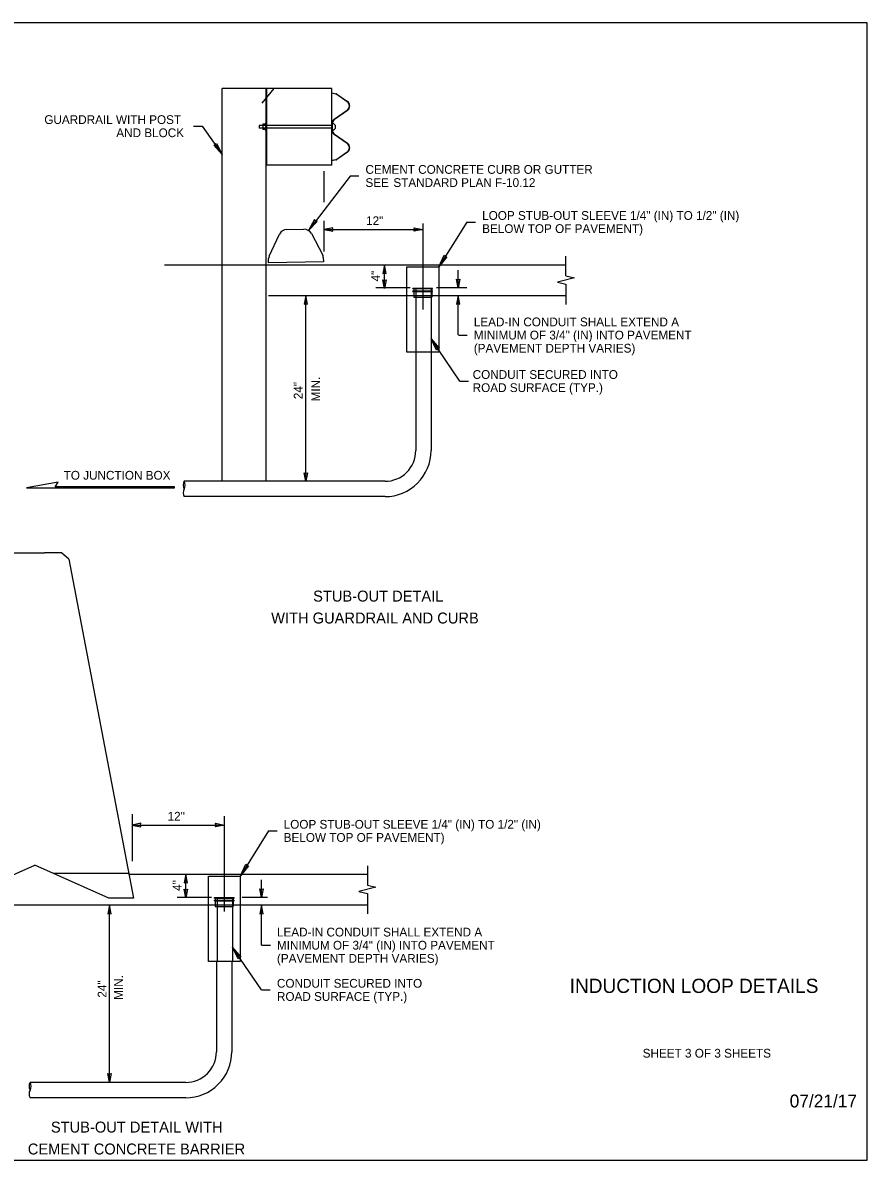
# Model space of a CAD drawing. Extents: x 99862 to 103151, y 100000 to 108153.
# Drawn here: x 101610 to 103151, y 106000 to 108076 of the extents above; entities that cross this region are included whole.
import ezdxf

# ---------------------------------------------------------------- set-up
doc = ezdxf.new("R2010")
doc.units = 0
for name, color, linetype in [('Level 1', 7, 'Continuous'), ('Level 10', 7, 'Continuous'), ('Level 11', 7, 'Continuous'), ('Level 15', 7, 'Continuous'), ('Level 18', 7, 'Continuous'), ('Level 2', 7, 'Continuous'), ('Level 20', 7, 'Continuous'), ('Level 22', 7, 'Continuous'), ('Level 27', 7, 'Continuous'), ('Level 5', 7, 'Continuous'), ('Level 60', 7, 'Continuous'), ('Level 62', 7, 'Continuous')]:
    doc.layers.add(name, color=color, linetype=linetype)

msp = doc.modelspace()

# ---------------------------------------------------------------- linework, layer by layer
at = {"layer": 'Level 1'}
for p, q in [((102053.9, 107955.6), (101973.9, 107955.6)), ((101973.9, 107633.3), (101973.9, 107955.6)), ((102053.9, 107634.9), (102053.9, 107955.6))]:
    msp.add_line(p, q, dxfattribs=at)
msp.add_lwpolyline([(99862, 105999.5), (103151, 105999.5), (103151, 108075.5), (99862, 108075.5)], close=True, dxfattribs=at)
at = {"layer": 'Level 10'}
for p, q in [((102173.9, 107955.6), (102053.9, 107955.6)), ((102054.9, 107815.6), (102054.9, 107955.6)), ((102173.9, 107815.6), (102173.9, 107955.6)), ((102173.9, 107815.6), (102053.9, 107815.6)), ((102601.1, 107633.3), (101868.6, 107633.3)), ((101973.9, 107238.6), (101973.9, 107633.3)), ((102053.9, 107238.6), (102053.9, 107634.9)), ((102319.5, 107577.3), (102057.9, 107577.3)), ((102361.1, 107577.3), (102319.4, 107577.3)), ((102601.1, 107577.3), (102361.1, 107577.3)), ((102238.8, 106521.1), (101803.4, 106521.1)), ((101957.1, 106465.1), (101334.5, 106465.1)), ((101998.8, 106465.1), (101957, 106465.1)), ((102238.8, 106465.1), (101998.8, 106465.1))]:
    msp.add_line(p, q, dxfattribs=at)
at = {"layer": 'Level 11'}
for p, q in [((101582.9, 107107.8), (101613.9, 107107.8)), ((101613.9, 107107.8), (101649.4, 107107.8)), ((101680.4, 107107.8), (101649.4, 107107.8)), ((101693.8, 107096.8), (101680.4, 107107.8)), ((101693.8, 107096.8), (101811.6, 106477.9)), ((101496.6, 106477.9), (101631.6, 106537.9)), ((101766.6, 106477.9), (101631.7, 106537.9)), ((101811.6, 106477.9), (101766.6, 106477.9))]:
    msp.add_line(p, q, dxfattribs=at)
for points in [[(102310.9, 107630.3), (102369.1, 107630.3), (102369.1, 107474.2), (102310.9, 107474.2)], [(101948.5, 106518), (102006.7, 106518), (102006.7, 106362), (101948.5, 106362)]]:
    msp.add_lwpolyline(points, close=True, dxfattribs=at)
at = {"layer": 'Level 15'}
for p, q in [((101921, 107886.7), (101937, 107886.7)), ((102223.1, 107795.8), (102207.1, 107795.8)), ((102339.6, 107709.1), (102339.9, 107552.2)), ((102420.1, 107711.8), (102369.1, 107630.3)), ((102420.1, 107711.8), (102436.1, 107711.8)), ((102269.8, 107591.6), (102269.8, 107633.7)), ((102404.3, 107591.9), (102404.3, 107623.9)), ((102316.5, 107591.6), (102253.8, 107591.6)), ((102420.3, 107591.7), (102364.5, 107591.7)), ((102404.3, 107505.7), (102404.3, 107577.5)), ((102407.3, 107421.5), (102354.8, 107498.8)), ((102404.9, 107505.5), (102420.9, 107505.5)), ((102407.3, 107421.5), (102423.3, 107421.5)), ((101809.5, 106631.1), (101809.5, 106545.6)), ((101977.5, 106627.3), (101977.5, 106453.5)), ((102057.9, 106600.6), (102006.9, 106518.8)), ((102057.9, 106600.6), (102073.9, 106600.6)), ((101907.4, 106479.3), (101907.4, 106521.5)), ((102238.8, 106537.1), (102238.8, 106501.6)), ((102045.6, 106479.3), (102045.6, 106511.3)), ((101954.1, 106479.3), (101891.4, 106479.3)), ((102056.4, 106479.1), (102009.9, 106479.1)), ((102238.8, 106486.1), (102238.8, 106449.1)), ((102045.6, 106391.9), (102045.6, 106464.9)), ((102045.1, 106310.4), (101992.6, 106387.6)), ((102045.6, 106391.9), (102061.6, 106391.9)), ((102045.1, 106310.4), (102061.1, 106310.4))]:
    msp.add_line(p, q, dxfattribs=at)
for points in [[(101937, 107886.7), (101973.9, 107835.1)], [(102207.1, 107795.8), (102130.9, 107696.6)], [(102159.8, 107748.3), (102159.8, 107804.5)], [(102159.8, 107658), (102159.8, 107714.2)], [(102159.8, 107698.2), (102339.8, 107698.2)], [(102601.1, 107613.8), (102616.6, 107609.9), (102585.6, 107602.2), (102601.1, 107598.3)], [(102126.3, 107238.6), (102126.3, 107577.3)], [(101809.5, 106611.3), (101977.5, 106611.3)], [(102238.8, 106501.6), (102254.3, 106497.7), (102223.3, 106489.9), (102238.8, 106486.1)], [(101767.8, 106142.3), (101767.8, 106465.1)]]:
    msp.add_lwpolyline(points, dxfattribs=at)
for points in [[(101973.9, 107835.1), (101958.2, 107851.9), (101961.2, 107852.8), (101963.1, 107855.4)], [(102130.9, 107696.6), (102147.1, 107712.9), (102144.1, 107713.9), (102142.4, 107716.5)], [(102159.8, 107698.2), (102175.5, 107695.1), (102174.8, 107698.2), (102175.5, 107701.2)], [(102339.8, 107698.2), (102324.1, 107695.1), (102324.8, 107698.2), (102324.1, 107701.2)], [(102369.1, 107630.3), (102378.8, 107651.2), (102380.8, 107648.7), (102383.8, 107648)], [(102269.8, 107633.7), (102266.7, 107618), (102269.8, 107618.7), (102272.9, 107618)], [(102269.8, 107590.7), (102266.7, 107606.4), (102269.8, 107605.7), (102272.9, 107606.4)], [(102404.3, 107591.9), (102401.2, 107607.6), (102404.3, 107606.9), (102407.4, 107607.6)], [(102126.3, 107577.3), (102123.2, 107561.6), (102126.3, 107562.3), (102129.4, 107561.6)], [(102404.3, 107577.5), (102401.2, 107561.8), (102404.3, 107562.5), (102407.4, 107561.8)], [(102354.8, 107498.8), (102369.9, 107481.5), (102366.9, 107480.7), (102365, 107478.1)], [(102126.3, 107238.6), (102123.2, 107254.3), (102126.3, 107253.6), (102129.4, 107254.3)], [(101809.5, 106611.3), (101825.2, 106608.3), (101824.4, 106611.3), (101825.2, 106614.4)], [(101977.5, 106611.3), (101961.7, 106608.3), (101962.5, 106611.3), (101961.7, 106614.4)], [(101907.4, 106521.5), (101904.3, 106505.7), (101907.4, 106506.5), (101910.5, 106505.7)], [(102006.9, 106518.8), (102016.5, 106539.7), (102018.4, 106537.2), (102021.5, 106536.6)], [(101907.4, 106478.4), (101904.3, 106494.1), (101907.4, 106493.4), (101910.5, 106494.1)], [(102045.6, 106479.3), (102042.5, 106495.1), (102045.6, 106494.3), (102048.7, 106495.1)], [(101767.8, 106465.1), (101764.7, 106449.4), (101767.8, 106450.1), (101770.9, 106449.4)], [(102045.6, 106464.9), (102042.5, 106449.2), (102045.6, 106449.9), (102048.7, 106449.2)], [(101992.6, 106387.6), (102007.8, 106370.3), (102004.7, 106369.5), (102002.8, 106366.9)], [(101767.8, 106142.3), (101764.7, 106158), (101767.8, 106157.3), (101770.9, 106158)]]:
    msp.add_lwpolyline(points, close=True, dxfattribs=at)
for centre, start, end in [((101916.4, 107231.6), 150, 210), ((101892.2, 107231.6), 330, 30), ((101916.4, 107217.6), 150, 210), ((101635.1, 106134.5), 150, 210), ((101635.1, 106120.5), 150, 210), ((101610.8, 106134.5), 330, 30)]:
    msp.add_arc(centre, 14, start, end, dxfattribs=at)
at = {"layer": 'Level 18'}
for p, q in [((102068.2, 107955.6), (102045.9, 107928.6)), ((102173.9, 107947.3), (102181.3, 107946)), ((102181.2, 107945.4), (102173.9, 107946.7)), ((102201.8, 107931.4), (102182.7, 107944.8)), ((102183.1, 107945.3), (102202.2, 107931.9)), ((102178.1, 107899.4), (102201.8, 107916)), ((102202.2, 107915.5), (102178.5, 107898.9)), ((102047.6, 107890.6), (102047.6, 107880.6)), ((102052.6, 107890.6), (102047.6, 107890.6)), ((102052.6, 107893.1), (102052.6, 107888.1)), ((102054, 107893.1), (102052.6, 107893.1)), ((102174.5, 107879.3), (102174.5, 107891.8)), ((102174.5, 107891.2), (102174.5, 107879.9)), ((102173.9, 107888.1), (102040.9, 107888.1)), ((102052.6, 107888.1), (102040.9, 107888.1)), ((102040.9, 107888.1), (102040.9, 107883.1)), ((102173.9, 107883.1), (102040.9, 107883.1)), ((102052.6, 107883.1), (102040.9, 107883.1)), ((102052.6, 107880.6), (102047.6, 107880.6)), ((102052.6, 107888.1), (102052.6, 107883.1)), ((102052.6, 107883.1), (102052.6, 107878.1)), ((102054, 107878.1), (102052.6, 107878.1)), ((102201.8, 107855.1), (102178.1, 107871.8)), ((102178.5, 107872.3), (102202.2, 107855.6)), ((102182.7, 107826.4), (102201.8, 107839.8)), ((102202.2, 107839.3), (102183.1, 107825.9)), ((102173.9, 107824.4), (102181.2, 107825.7)), ((102181.3, 107825.1), (102173.9, 107823.8))]:
    msp.add_line(p, q, dxfattribs=at)
for centre, radius, start, end in [((102180.6, 107941.7), 3.75, 54.852, 80), ((102180.6, 107941.7), 4.38, 54.852, 80), ((102196.4, 107923.7), 9.38, 305.1461, 54.8378), ((102196.4, 107923.7), 10, 305.1461, 54.8378), ((102183.9, 107891.2), 10, 125.1612, 179.9985), ((102183.9, 107891.2), 9.38, 125.1612, 180), ((102174.5, 107885.6), 6.25, 270, 90), ((102183.9, 107879.9), 10, 180.0103, 234.8388), ((102183.9, 107879.9), 9.38, 180.0103, 234.8388), ((102196.4, 107847.4), 9.38, 305.1426, 54.8569), ((102196.4, 107847.4), 10, 305.1426, 54.8569), ((102180.6, 107829.4), 3.75, 280, 305.1437), ((102180.6, 107829.4), 4.38, 280, 305.1437)]:
    msp.add_arc(centre, radius, start, end, dxfattribs=at)
at = {"layer": 'Level 2'}
for p, q in [((102601.1, 107613.8), (102601.1, 107649.3)), ((102321.8, 107591.2), (102357.8, 107591.2)), ((102321.8, 107590.2), (102321.8, 107591.2)), ((102321.8, 107590.2), (102357.8, 107590.2)), ((102321.8, 107586.2), (102357.8, 107586.2)), ((102321.8, 107585.2), (102321.8, 107586.2)), ((102321.8, 107585.2), (102357.8, 107585.2)), ((102323.4, 107590.2), (102323.4, 107586.2)), ((102323.4, 107585.2), (102323.4, 107574.8)), ((102356.2, 107590.2), (102356.2, 107586.2)), ((102356.2, 107585.2), (102356.2, 107574.8)), ((102357.8, 107590.2), (102357.8, 107591.2)), ((102357.8, 107585.2), (102357.8, 107586.2)), ((102601.1, 107598.3), (102601.1, 107561.3)), ((102323.4, 107574.8), (102356.2, 107574.8)), ((101803, 106522.9), (101665.4, 106522.9)), ((101959.4, 106479), (101995.5, 106479)), ((101959.4, 106478), (101959.4, 106479)), ((101995.5, 106478), (101995.5, 106479)), ((101959.4, 106478), (101995.5, 106478)), ((101959.4, 106474), (101995.5, 106474)), ((101959.4, 106473), (101959.4, 106474)), ((101959.4, 106473), (101995.5, 106473)), ((101961, 106478), (101961, 106474)), ((101961, 106473), (101961, 106462.5)), ((101961, 106462.5), (101993.9, 106462.5)), ((101993.9, 106478), (101993.9, 106474)), ((101993.9, 106472.9), (101993.9, 106462.5)), ((101995.5, 106473), (101995.5, 106474))]:
    msp.add_line(p, q, dxfattribs=at)
at = {"layer": 'Level 20'}
msp.add_lwpolyline([(101886.7, 107228.3), (101669, 107228.3), (101674, 107236.9), (101616.3, 107226.7), (101886.7, 107226.7)], close=True, dxfattribs=at)
at = {"layer": 'Level 22'}
for p, q in [((102350.8, 107590.2), (102329.5, 107590.2)), ((101988.4, 106478), (101967.1, 106478))]:
    msp.add_line(p, q, dxfattribs=at)
at = {"layer": 'Level 27'}
for points in [[(102059.2, 107649.5), (102078.2, 107689.5)], [(102091.5, 107698.1), (102122.9, 107698.7), (102122.9, 107698.7)], [(102136.5, 107690.7), (102157.1, 107651.5)], [(102158.2, 107647), (102158.4, 107639.4), (102058.4, 107637.4), (102058.3, 107645)]]:
    msp.add_lwpolyline(points, dxfattribs=at)
for centre, radius, start, end in [((102091.8, 107683.1), 15, 91.1458, 154.5807), ((102123.2, 107683.7), 15, 27.7108, 91.1455), ((102068.3, 107645.2), 10, 154.5807, 181.1458), ((102148.2, 107646.8), 10, 1.1458, 27.7108)]:
    msp.add_arc(centre, radius, start, end, dxfattribs=at)
at = {"layer": 'Level 5'}
for p, q in [((102326.8, 107474.2), (102326.8, 107294.6)), ((102354.8, 107474.2), (102354.8, 107294.6)), ((102058.2, 107238.6), (101974.1, 107238.6)), ((102270.8, 107238.6), (102053.9, 107238.6)), ((101973.9, 107210.6), (101904.3, 107210.6)), ((102058.2, 107210.6), (101974.1, 107210.6)), ((102270.8, 107210.6), (102053.9, 107210.6)), ((101992.4, 106478), (101992.4, 106362.2)), ((101963.1, 106363), (101963.1, 106197.5)), ((101991.1, 106363), (101991.1, 106197.5)), ((101907.1, 106141.5), (101623, 106141.5)), ((101907.1, 106113.5), (101623, 106113.5))]:
    msp.add_line(p, q, dxfattribs=at)
for centre, radius, end in [((102270.8, 107294.6), 84, 0.0003), ((102270.8, 107294.6), 56, 0.0002), ((101907.1, 106197.5), 84, 0.0003), ((101907.1, 106197.5), 56, 0.0002)]:
    msp.add_arc(centre, radius, 270, end, dxfattribs=at)
for points in [[(102326.8, 107590), (102326.8, 107579.6), (102326.8, 107543.2), (102326.8, 107473.2)], [(101973.9, 107238.6), (101954.4, 107238.6), (101930.6, 107238.6), (101904.3, 107238.6)], [(101964.4, 106477.8), (101964.4, 106433.1), (101964.4, 106397.7), (101964.4, 106362.2)]]:
    msp.add_open_spline(points, degree=2, dxfattribs=at)
msp.add_spline([(102354.8, 107590), (102354.8, 107485.2), (102354.8, 107473.2)], degree=3, dxfattribs=at)
at = {"layer": 'Level 60'}
msp.add_line((103151, 108075.5), (103151, 108075.5), dxfattribs=at)
msp.add_line((103151, 108075.5), (103151, 108075.5), dxfattribs=at)

# ---------------------------------------------------------------- texts
at = {"layer": 'Level 15'}
msp.add_text('07/21/17', height=23.62, dxfattribs=at).set_placement((103009.4, 106095.8))
at = {"layer": 'Level 18'}
for s, rotation, p in [('GUARDRAIL WITH POST', 360, (101649, 107890.7)), (' AND BLOCK', 360, (101774.4, 107866.7)), ('CEMENT CONCRETE CURB OR GUTTER', 0, (102235.1, 107799.8)), ('SEE ', 0, (102235.1, 107775.8)), ('STANDARD PLAN F-10.12', 0, (102286.1, 107775.8)), ('4" ', 90, (102261.8, 107603.3)), ('24" ', 90, (102120.3, 107388.5)), ('MIN.', 90, (102152.3, 107384.4)), ('TO JUNCTION BOX', 360, (101684.3, 107241.6)), ('4" ', 90, (101899.4, 106491.1)), ('MIN.', 90, (101792.4, 106292.3)), ('24" ', 90, (101762.4, 106296.3))]:
    msp.add_text(s, height=16, rotation=rotation, dxfattribs=at).set_placement(p)
for s, p in [('LOOP STUB-OUT SLEEVE 1/4" (IN) TO 1/2" (IN)', (102448.1, 107715.8)), ('12" ', (102236.3, 107706.2)), ('BELOW TOP OF PAVEMENT)', (102448.1, 107691.8)), ('LEAD-IN CONDUIT SHALL EXTEND A', (102432.9, 107521.5)), ('MINIMUM OF 3/4" (IN) INTO PAVEMENT', (102432.9, 107497.5)), ('(PAVEMENT DEPTH VARIES)', (102432.9, 107473.5)), ('CONDUIT SECURED INTO ', (102430.8, 107425.5)), ('ROAD SURFACE (TYP.)', (102430.8, 107401.5)), ('12" ', (101874, 106619.3)), ('LOOP STUB-OUT SLEEVE 1/4" (IN) TO 1/2" (IN)', (102085.9, 106604.6)), ('BELOW TOP OF PAVEMENT)', (102085.9, 106580.6)), ('LEAD-IN CONDUIT SHALL EXTEND A', (102073.6, 106407.9)), ('MINIMUM OF 3/4" (IN) INTO PAVEMENT', (102073.6, 106383.9)), ('(PAVEMENT DEPTH VARIES)', (102073.6, 106359.9)), ('CONDUIT SECURED INTO ', (102073.6, 106314.4)), ('ROAD SURFACE (TYP.)', (102073.6, 106290.4))]:
    msp.add_text(s, height=16, dxfattribs=at).set_placement(p)
at = {"layer": 'Level 20'}
for s, p in [(' STUB-OUT DETAIL', (102132.2, 107019.1)), ('WITH GUARDRAIL AND CURB', (102063, 106979.1)), ('STUB-OUT DETAIL WITH', (101661, 106050)), ('CEMENT CONCRETE BARRIER', (101618.8, 106010))]:
    msp.add_text(s, height=20, dxfattribs=at).set_placement(p)
at = {"layer": 'Level 62'}
for s, height, p in [('INDUCTION LOOP DETAILS', 26, (102607.9, 106304.8)), ('SHEET 3 OF 3 SHEETS', 16, (102741.1, 106186.8))]:
    msp.add_text(s, height=height, dxfattribs=at).set_placement(p)

doc.saveas('drawing.dxf')
